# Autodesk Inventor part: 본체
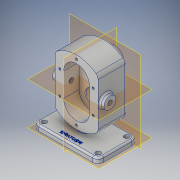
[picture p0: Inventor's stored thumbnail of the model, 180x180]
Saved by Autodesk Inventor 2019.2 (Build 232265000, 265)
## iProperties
Created: 2019-03
Part Number: 본체
Material: 알루미늄 6061
Document SubType Name: Modeling
Designer: User
Density: 2.7 g/cm^3
Appearance: 알루미늄 - 평지
Mass: 1187.18 g
Surface Area: 719.275 cm^2
Volume: 439.697 cm^3
Author: User
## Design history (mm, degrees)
sketch "스케치1"
  geometry: L1 (0, -14.6)-(0, 87.6) reference; L2 (84, 0)-(-84, 0) reference; L3 (60, 73)-(-60, 73); L4 (-60, 73)-(-60, 0); L5 (-60, 0)-(60, 0); L6 (60, 0)-(60, 73); L7 (60, 73)-(-60, 0); L8 (-60, 73)-(60, 0); 2 further points
  constraints: 12 end point, 3 midpoint, 2 parallel, 1 collinear, 1 horizontal, 1 perpendicular
  dimensions: "d0" = 120 distance of L5.end L4.end; "d1" = 73 distance of L4.end L3.end
extrude "돌출1" new body sketch "스케치1" distance "d2" = 10; taper "d3" = 0 deg
sketch "스케치2"
  geometry: L1 (-40, 138)-(40, 138); L2 (40, 122.721)-(40, 33.279); L3 (40, 18)-(-40, 18); L4 (-40, 33.279)-(-40, 122.721); L5 (-40, 138)-(40, 18); L6 (40, 138)-(-40, 18); L7 (0, -40.2)-(0, 241.2) reference; L8 (-111.6, 0)-(88.6, 0) reference; L9 (0, 241.2)-(0, -40.2) reference; L10 (-60, 0)-(60, 0) reference; A1 r 60 centre (0, 78) between (40, 122.721) and (-40, 122.721); A2 r 60 centre (0, 78) between (-40, 33.279) and (40, 33.279); 3 further points
  constraints: 12 end point, 4 point on circle, 3 midpoint, 3 parallel, 2 centre point, 2 coincident, 1 horizontal, 1 perpendicular, 1 point on line, 1 tangent
  dimensions: "d5" = 138 distance between parallel lines of L10 L1; "d6" = 78 distance from line of L8 point (0, 78); "d7" = 60 radius of A1; "d8" = 60 radius of A2; "d9" = 80 distance between parallel lines of L2 L4
extrude "돌출2" join sketch "스케치2" distance "d10" = 53; taper "d11" = 0 deg
sketch "스케치4"
  geometry: L1 (-6, -43)-(6, -43); L2 (6, -43)-(6, 0); L3 (6, 0)-(-6, 0); L4 (-6, 0)-(-6, -43); L5 (-6, -43)-(6, 0); L6 (6, -43)-(-6, 0); L7 (0, 14.6)-(0, -87.6) reference; L8 (-84, 0)-(84, 0) reference; 3 further points
  constraints: 12 end point, 3 midpoint, 2 parallel, 1 collinear, 1 horizontal, 1 perpendicular, 1 point on line
  dimensions: "d17" = 12 distance of L1.start L1.end; "d18" = 43 distance of L3.end L1.start
extrude "돌출4" join sketch "스케치4" distance "d19" = 78; taper "d20" = 0 deg
sketch "스케치3"
  geometry: L1 (0, -27.6)-(0, 165.6) reference; L2 (-84, 0)-(84, 0) reference; L3 (0, 100)-(0, 56); L4 (-24, 100)-(-24, 56); L5 (24, 56)-(24, 100); A1 r 24 centre (0, 100) between (24, 100) and (-24, 100); A2 r 24 centre (0, 56) between (-24, 56) and (24, 56); 2 further points
  constraints: 8 end point, 4 point on circle, 4 tangent, 2 centre point, 2 point on line, 1 midpoint, 1 parallel
  dimensions: "d12" = 24 radius of A1; "d13" = 44 distance of L5.start L5.end; "d14" = 78 distance from line of L2 point (0, 78)
extrude "돌출3" cut sketch "스케치3" distance "d15" = 29; taper "d16" = 0 deg
sketch "스케치5"
  geometry: L1 (60, -27.6)-(60, 165.6) reference; L2 (144, 0)-(-24, 0) reference; C1 r 19 at (60, 100); 1 further point
  constraints: 1 centre point, 1 point on line
  dimensions: "d22" = 38 diameter of C1; "d23" = 100 distance from line of L2 C1.centre
extrude "돌출5" join sketch "스케치5" distance "d24" = 17; taper "d25" = 0 deg
sketch "스케치6"
  geometry: A1 r 24 centre (0, 100) between (24, 100) and (-24, 100) reference; 2 further points
  constraints: 1 coincident
hole "구멍1" sketch "스케치6" at (0, 100) diameter "d26" = 17; stored, may be unused: countersink angle "d30" = 90 deg, drill point angle "d32" = 0 deg; dims "d27" = 6, "d28" = 25, "d29" = 15, "d31" = 10
sketch "스케치7"
  geometry: C1 r 19 at (0, 0) reference; 2 further points
  constraints: 1 coincident
hole "구멍2" sketch "스케치7" at (0, 0) diameter "d33" = 28; stored, may be unused: countersink angle "d37" = 90 deg, drill point angle "d39" = 0 deg; dims "d34" = 6, "d35" = 25, "d36" = 15, "d38" = 7.3
sketch "스케치8"
  geometry: A1 r 24 centre (0, 56) between (-24, 56) and (24, 56) reference; 2 further points
  constraints: 1 coincident
hole "구멍3" sketch "스케치8" at (0, 56) diameter "d40" = 25; stored, may be unused: countersink angle "d44" = 90 deg, drill point angle "d46" = 0 deg; dims "d41" = 6, "d42" = 25, "d43" = 15, "d45" = 15
sketch "스케치9"
  geometry: L1 (0, -35)-(0, 91) reference; L2 (-27.6, 0)-(165.6, 0) reference; L3 (56, 53)-(100, 53) reference; C1 r 11 at (78, 39); 1 further point
  constraints: 1 centre point
  dimensions: "d47" = 22 diameter of C1; "d48" = 78 distance from line of L1 C1.centre; "d49" = 14 distance from line of L3 C1.centre
extrude "돌출6" join sketch "스케치9" distance "d50" = 8; taper "d51" = 0 deg
sketch "스케치10"
  geometry: C1 r 11 at (0, 0) reference; 2 further points
  constraints: 1 coincident
hole "구멍4" sketch "스케치10" at (0, 0) diameter "d52" = 8.376; stored, may be unused: countersink angle "d56" = 90 deg, drill point angle "d58" = 0 deg; dims "d53" = 30, "d54" = 25, "d55" = 15, "d57" = 27.3
sketch "스케치11"
  geometry: L1 (0, -27.6)-(0, 165.6) reference; L2 (-51, 100)-(51, 100); A1 r 31 centre (0, 100) between (0, 131) and (31, 100); A2 r 24 centre (0, 100) between (24, 100) and (-24, 100) reference; 2 further points
  constraints: 3 point on circle, 3 point on line, 2 end point, 1 centre point, 1 concentric, 1 horizontal, 1 midpoint
  dimensions: "d59" = 62 diameter of A1
hole "구멍6" sketch "스케치11" at (0, 131), (31, 100), (-31, 100) diameter "d67" = 4.134; stored, may be unused: countersink angle "d71" = 90 deg, drill point angle "d73" = 118 deg; dims "d68" = 10, "d69" = 25, "d70" = 15, "d72" = 12
node "오프셋 78"
fillet "모깎기1" dims "d75" = 10
sketch "스케치12"
  geometry: A1 r 10 centre (-50, -63) between (-60, -63) and (-50, -73) reference; A2 r 10 centre (50, -63) between (50, -73) and (60, -63) reference; A3 r 10 centre (50, -10) between (60, -10) and (50, 0) reference; A4 r 10 centre (-50, -10) between (-50, 0) and (-60, -10) reference; 5 further points
  constraints: 4 coincident
hole "구멍7" sketch "스케치12" at (-50, -63), (50, -63), (50, -10), (-50, -10) diameter "d76" = 9; stored, may be unused: countersink angle "d80" = 90 deg, drill point angle "d82" = 118 deg; dims "d77" = 10, "d78" = 25, "d79" = 15, "d81" = 12
sketch "스케치13"
  geometry: L1 (114, -9.7)-(114, -17) reference; L2 (81, -17)-(119, -17) reference; L3 (114, -16.3)-(114.404, -17); L4 (114, -17)-(114.404, -17); L5 (114, -16.3)-(114, -17); L6 (100, 106)-(100, -45); L7 (0, 136.2)-(0, -75.2) reference; 1 further point
  constraints: 8 end point, 2 collinear, 2 point on line, 1 vertical
  dimensions: "d84" = 30 deg angle of L3 L5; "d85" = 0.7 distance from line of L2 L3.start; "d86" = 100 distance between parallel lines of L7 L6
revolve "회전1" sketch "스케치13" stored, may be unused: angle "d87" = 90 deg
chamfer "모따기1" distance "d88" = 1; stored, may be unused: second distance "d89" = 2, angle "d90" = 45 deg
fillet "모깎기2" dims "d91" = 0.5
fillet "모깎기4" dims "d93" = 10
fillet "모깎기3" dims "d92" = 3
fillet "모깎기5" dims "d94" = 3
fillet "모깎기6" dims "d95" = 3
fillet "모깎기7" dims "d96" = 3
sketch "스케치14"
  geometry: L1 (-50, -73)-(50, -73) reference; L2 (-60, -10)-(-60, -63) reference; 2 further points
  constraints: 1 other
  dimensions: "d97" = 10 distance from line of L1 point (0, -63); "d98" = 60 distance from line of L2 point (0, -63)
feature "엠보싱1" sketch "스케치14" dims "d99" = 0.5, "d100" = 0
node "솔리드1"
mirror "미러2"
mirror "미러3"
other parameters: "d74" = 78
